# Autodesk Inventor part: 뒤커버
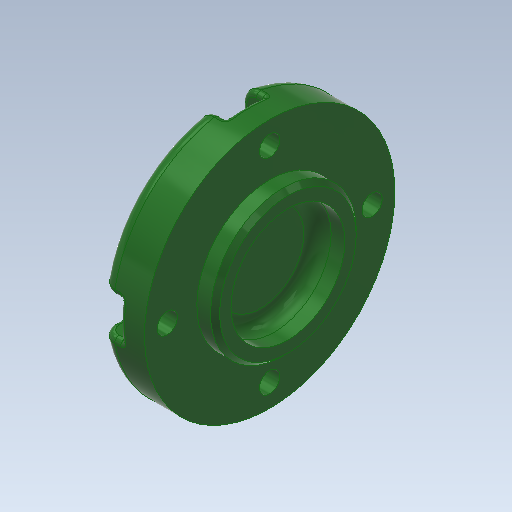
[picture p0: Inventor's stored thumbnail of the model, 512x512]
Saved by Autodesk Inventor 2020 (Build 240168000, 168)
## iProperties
Created: 2015-11
Part Number: 뒤커버
Material: 알루미늄 6061
Document SubType Name: Modeling
Designer: mduedu
Density: 1 g/cm^3
Appearance: 매끄러움 - 짙은 산림 녹색
Author: mduedu
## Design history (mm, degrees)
sketch "스케치1"
  geometry: L1 (-7, 0)-(7, 0); L2 (-7, 0)-(-7, 27.5); L3 (-7, 27.5)-(3, 27.5); L4 (3, 27.5)-(3, 16); L5 (3, 16)-(7, 16); L6 (7, 16)-(7, 0); 2 further points
  constraints: 12 end point, 3 perpendicular, 2 parallel, 1 coincident, 1 horizontal, 1 midpoint
  dimensions: "d0" = 14 distance of L1.start L1.end; "d1" = 55 diameter of L3 L1; "d2" = 4 distance of L4.end L5.end; "d3" = 32 diameter of L5 L1
revolve "회전1" sketch "스케치1" stored, may be unused: angle "d4" = 90 deg
hole "구멍1" diameter "d7" = 25; stored, may be unused: countersink angle "d11" = 90 deg, drill point angle "d13" = 0 deg; dims "d8" = 6, "d9" = 4, "d10" = 2, "d12" = 6, "d61" = 10, "d62" = 10
fillet "모깎기2" dims "d36" = 3
fillet "모깎기3" dims "d37" = 3
sketch "스케치2" dims "d39" = 45
  geometry: C1 r 12.846 at (0, 0) reference; C2 r 24.5 at (0, 0) reference; 6 further points
  constraints: 2 vertical alignment, 1 coincident, 7 other
  dimensions: "d42" = 360 deg dimension on point (0, 0) point (0, 22.5) (derived)
sketch "스케치3"
  geometry: 8 further points
  constraints: 4 coincident
hole "구멍4" sketch "스케치3" at (-22.5, 0), (0, -22.5), (22.5, 0), (0, 22.5) diameter "d44" = 4.5; stored, may be unused: countersink angle "d48" = 90 deg, drill point angle "d50" = 0 deg; dims "d45" = 6, "d46" = 8, "d47" = 4.6, "d49" = 8
sketch "스케치4"
  geometry: L1 (-4, 0)-(-4, -4.708); L2 (4, 0)-(4, -4.708); A1 r 4 centre (0, 0) between (-4, 0) and (4, 0) reference; A2 r 27.5 centre (0, 22.5) between (-4, -4.708) and (4, -4.708) reference; 3 further points
  constraints: 4 end point, 4 point on circle, 2 tangent, 1 parallel, 1 vertical
extrude "돌출1" cut sketch "스케치4" extent not by distance; stored distance "d51" = 0; taper "d52" = 0 deg
fillet "모깎기5" dims "d56" = 0.3
fillet "모깎기6" dims "d57" = 1
chamfer "모따기2" distance "d63" = 1; stored, may be unused: second distance "d64" = 2, angle "d65" = 45 deg
node "솔리드1"
pattern_circular "원형 패턴1" dims angle "d54" = 360 deg
